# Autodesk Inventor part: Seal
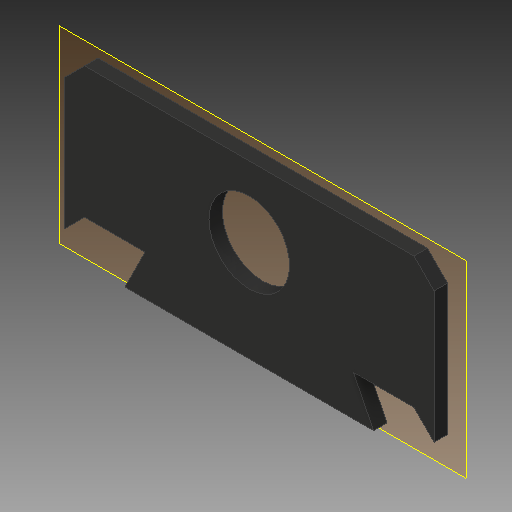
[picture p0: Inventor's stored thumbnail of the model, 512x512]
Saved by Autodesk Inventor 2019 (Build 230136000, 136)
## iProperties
Created: 2018-11
Part Number: Seal
Material: Rubber
Document SubType Name: Modeling
Designer: Synergysoft
Density: 0.93 g/cm^3
Appearance: Rubber - Black
Mass: 2.16393 g
Surface Area: 27.4898 cm^2
Volume: 2.32681 cm^3
Author: Synergysoft
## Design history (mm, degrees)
workplane "Work Plane1"
sketch "Sketch1"
  geometry: L1 (-27.5, 19.25)-(-24.5, 22.25) reference; L2 (-27.5, 19.25)-(-27.5, -0.25) reference; L3 (-24.5, 2.75)-(-27.5, -0.25) reference; L4 (-15.5, 2.75)-(-24.5, 2.75) reference; L5 (-18.5, -3.25)-(-15.5, 2.75) reference; L6 (18.5, -3.25)-(-18.5, -3.25) reference; L7 (15.5, 2.75)-(18.5, -3.25) reference; L8 (24.5, 2.75)-(15.5, 2.75) reference; L9 (27.5, -0.25)-(24.5, 2.75) reference; L10 (27.5, -0.25)-(27.5, 19.25) reference; L11 (24.5, 22.25)-(27.5, 19.25) reference; L12 (-24.5, 22.25)-(24.5, 22.25) reference; C1 r 6 at (0, 11.75) reference; 1 further point
extrude "Extrusion1" new body sketch "Sketch1" distance "d0" = 2; taper "d1" = 0 deg
body "Solid1"
node "Reference1"
